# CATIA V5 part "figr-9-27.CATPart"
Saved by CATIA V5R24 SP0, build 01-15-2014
Part number: Part1
Bounding box of the stored display mesh (mm): x -75 to 75, y -50 to 50, z 0 to 40
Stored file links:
  D:\KAVITA\CATIA V5-6R2014 Project_ Kavita\CATIA V5-6R2014_partfiles\Partfiles\c09_catia_v5-6r2014_prt\figr-9-27.CATPart
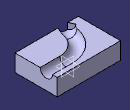
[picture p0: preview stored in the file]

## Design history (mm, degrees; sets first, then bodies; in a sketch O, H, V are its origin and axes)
Body1 (main body)
  Sketch1 on xy-plane, origin (0, 0, 0), H (1, 0, 0), V (0, 1, 0)
    line L1 (-75, 50) -> (75, 50)
    line L2 (75, 50) -> (75, -50)
    line L3 (75, -50) -> (-75, -50)
    line L4 (-75, -50) -> (-75, 50)
    axis line L5 (75, -50) -> (-75, 50)
    length L2 = 100
    length L3 = 150
    horizontal: L1 H, L3 H
    vertical: L2 V, L4 V
    midpoint: O L5
  Pad1: profile Sketch1, direction (0, 0, 1), length 40
  Sketch2 on face of Pad1, origin (75, 0, 0), H (0, 1, 0), V (0, 0, 1)
    arc A1 centre (24.1478, 40) radius 14.6047 from (9.543, 40) to (38.7525, 40) ccw
    point P1 (24.1478, 40)
    reference projected point E1 (24.1478, 40) from vertex of Sketch3
    line L1 (9.543, 40) -> (38.7525, 40)
    coincidence: P1 E1
    horizontal: L1 H
  Sketch3 on face of Pad1, origin (0, 0, 40), H (1, 0, 0), V (0, 1, 0)
    point P1 (75, 24.1478)
    line L1 (75, 24.1478) -> (28.6577, 24.1478)
    arc A1 centre (28.6577, -39.2062) radius 63.354 from (28.6577, 24.1478) to (-33.8383, -28.8149) ccw
    arc A2 centre (-62.192, -24.1005) radius 28.7429 from (-33.8383, -28.8149) to (-49.7271, -50) cw
    point P6 (-49.7271, -50)
    reference projected line E1 (75, -50) -> (75, 50) from edge [face of Pad1 | face of Pad1]
    reference projected line E2 (-75, -50) -> (75, -50) from edge [face of Pad1 | face of Pad1]
    horizontal: L1 H
    tangency: A1 L1, A2 A1
    coincidence: P1 E1, P6 E2
  Slot1: profile Sketch2, centre curve Sketch3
